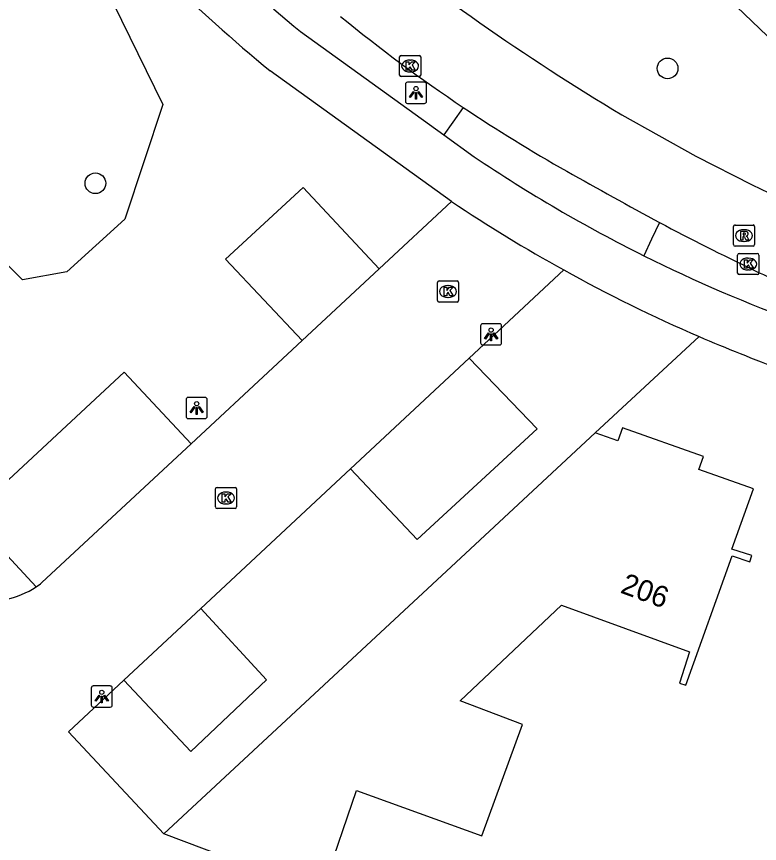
# Model space of a CAD drawing. Extents: x 155275 to 156263, y 382654 to 383635.
# Drawn here: x 155747.08 to 155782.2, y 383032.92 to 383071.98 of the extents above; entities that cross this region are included whole.
import ezdxf

# ---------------------------------------------------------------- set-up
doc = ezdxf.new("R2010")
doc.units = 0
for name, color, linetype in [('IMGEO_Berm_groen', 7, 'Continuous'), ('IMGEO_Boom', 7, 'Continuous'), ('IMGEO_Groenvoorziening', 7, 'Continuous'), ('IMGEO_Kolk', 7, 'Continuous'), ('IMGEO_Lichtpunt', 7, 'Continuous'), ('IMGEO_Pand', 7, 'Continuous'), ('IMGEO_Pand_nummerreeks', 7, 'Continuous'), ('IMGEO_Parkeervlak_open', 7, 'Continuous'), ('IMGEO_Rijbaan_lokaal_gesloten', 7, 'Continuous'), ('IMGEO_Rijbaan_lokaal_open', 7, 'Continuous'), ('IMGEO_Rioolput', 7, 'Continuous'), ('IMGEO_Voetpad_open', 7, 'Continuous')]:
    doc.layers.add(name, color=color, linetype=linetype)

msp = doc.modelspace()

# ---------------------------------------------------------------- linework, layer by layer
at = {"layer": 'IMGEO_Berm_groen'}
for points in [[(155812.91, 383066.171), (155809.833, 383066.391), (155801.367, 383066.998), (155792.138, 383071.742), (155786.195, 383067.61), (155775.328, 383078.007), (155762.855, 383086.013), (155746.776, 383104.071), (155742.231, 383112.533), (155736.041, 383119.787), (155734.812, 383124.613), (155732.465, 383124.934), (155728.264, 383135.475), (155728.221, 383137.957)], [(155779.344, 383056.868), (155774.441, 383052.316)]]:
    msp.add_lwpolyline(points, dxfattribs=at)
at = {"layer": 'IMGEO_Boom'}
for centre in [(155777.857, 383069.535), (155750.811, 383064.105)]:
    msp.add_circle(centre, 0.489, dxfattribs=at)
at = {"layer": 'IMGEO_Groenvoorziening'}
msp.add_lwpolyline([(155742.897, 383084.163), (155743.556, 383083.253), (155751.257, 383073.438), (155753.999, 383067.834), (155752.202, 383062.412), (155749.467, 383059.929), (155747.367, 383059.538), (155740.681, 383066.236), (155731.593, 383071.669), (155723.652, 383083.455), (155716.242, 383095.037), (155715.841, 383102.729), (155713.131, 383103.008)], dxfattribs=at)
at = {"layer": 'IMGEO_Kolk'}
for p, q in [((155765.262, 383070.147), (155766.114, 383070.147)), ((155765.187, 383069.221), (155765.187, 383070.073)), ((155765.675, 383069.927), (155765.7, 383069.927)), ((155766.188, 383070.073), (155766.188, 383069.221)), ((155765.698, 383069.367), (155765.673, 383069.367)), ((155766.114, 383069.147), (155765.262, 383069.147)), ((155781.17, 383059.865), (155781.17, 383060.717)), ((155781.245, 383060.791), (155782.097, 383060.791)), ((155782.171, 383060.717), (155782.171, 383059.865)), ((155781.658, 383060.571), (155781.683, 383060.571)), ((155781.681, 383060.011), (155781.656, 383060.011)), ((155782.097, 383059.791), (155781.245, 383059.791)), ((155766.978, 383058.567), (155766.978, 383059.419)), ((155767.053, 383059.493), (155767.905, 383059.493)), ((155767.466, 383059.273), (155767.491, 383059.273)), ((155767.979, 383059.419), (155767.979, 383058.567)), ((155767.905, 383058.493), (155767.053, 383058.493)), ((155767.489, 383058.713), (155767.464, 383058.713)), ((155756.486, 383048.813), (155756.486, 383049.665)), ((155756.561, 383049.739), (155757.413, 383049.739)), ((155756.974, 383049.519), (155756.999, 383049.519)), ((155757.487, 383049.665), (155757.487, 383048.813)), ((155757.413, 383048.739), (155756.561, 383048.739)), ((155756.997, 383048.959), (155756.972, 383048.959))]:
    msp.add_line(p, q, dxfattribs=at)
for points in [[(155765.262, 383070.147), (155766.114, 383070.147)], [(155765.187, 383069.221), (155765.187, 383070.073)], [(155765.508, 383069.847), (155765.631, 383069.847), (155765.631, 383069.696), (155765.761, 383069.847), (155765.925, 383069.847), (155765.779, 383069.696), (155765.932, 383069.447), (155765.78, 383069.447), (155765.695, 383069.611), (155765.631, 383069.544), (155765.631, 383069.447), (155765.508, 383069.447), (155765.508, 383069.847)], [(155766.188, 383070.073), (155766.188, 383069.221)], [(155766.114, 383069.147), (155765.262, 383069.147)], [(155781.17, 383059.865), (155781.17, 383060.717)], [(155781.245, 383060.791), (155782.097, 383060.791)], [(155782.171, 383060.717), (155782.171, 383059.865)], [(155781.491, 383060.491), (155781.614, 383060.491), (155781.614, 383060.34), (155781.744, 383060.491), (155781.908, 383060.491), (155781.762, 383060.34), (155781.915, 383060.091), (155781.763, 383060.091), (155781.678, 383060.255), (155781.614, 383060.188), (155781.614, 383060.091), (155781.491, 383060.091), (155781.491, 383060.491)], [(155782.097, 383059.791), (155781.245, 383059.791)], [(155766.978, 383058.567), (155766.978, 383059.419)], [(155767.053, 383059.493), (155767.905, 383059.493)], [(155767.299, 383059.193), (155767.422, 383059.193), (155767.422, 383059.042), (155767.552, 383059.193), (155767.716, 383059.193), (155767.57, 383059.042), (155767.723, 383058.793), (155767.571, 383058.793), (155767.486, 383058.957), (155767.422, 383058.89), (155767.422, 383058.793), (155767.299, 383058.793), (155767.299, 383059.193)], [(155767.979, 383059.419), (155767.979, 383058.567)], [(155767.905, 383058.493), (155767.053, 383058.493)], [(155756.486, 383048.813), (155756.486, 383049.665)], [(155756.561, 383049.739), (155757.413, 383049.739)], [(155756.807, 383049.439), (155756.93, 383049.439), (155756.93, 383049.288), (155757.06, 383049.439), (155757.224, 383049.439), (155757.078, 383049.288), (155757.231, 383049.039), (155757.079, 383049.039), (155756.994, 383049.203), (155756.93, 383049.136), (155756.93, 383049.039), (155756.807, 383049.039), (155756.807, 383049.439)], [(155757.487, 383049.665), (155757.487, 383048.813)], [(155757.413, 383048.739), (155756.561, 383048.739)]]:
    msp.add_lwpolyline(points, dxfattribs=at)
for centre, start, end in [((155765.264, 383070.071), 91.552, 178.448), ((155765.264, 383070.071), 91.552, 178.448), ((155766.112, 383070.071), 1.552, 88.448), ((155766.112, 383070.071), 1.552, 88.448), ((155765.264, 383069.223), 181.552, 268.448), ((155765.264, 383069.223), 181.552, 268.448), ((155766.112, 383069.223), 271.552, 358.448), ((155766.112, 383069.223), 271.552, 358.448), ((155781.247, 383060.715), 91.552, 178.448), ((155781.247, 383060.715), 91.552, 178.448), ((155782.095, 383060.715), 1.552, 88.448), ((155782.095, 383060.715), 1.552, 88.448), ((155781.247, 383059.867), 181.552, 268.448), ((155781.247, 383059.867), 181.552, 268.448), ((155782.095, 383059.867), 271.552, 358.448), ((155782.095, 383059.867), 271.552, 358.448), ((155767.055, 383059.417), 91.552, 178.448), ((155767.055, 383059.417), 91.552, 178.448), ((155767.903, 383059.417), 1.552, 88.448), ((155767.903, 383059.417), 1.552, 88.448), ((155767.055, 383058.569), 181.552, 268.448), ((155767.055, 383058.569), 181.552, 268.448), ((155767.903, 383058.569), 271.552, 358.448), ((155767.903, 383058.569), 271.552, 358.448), ((155756.563, 383049.663), 91.552, 178.448), ((155756.563, 383049.663), 91.552, 178.448), ((155757.411, 383049.663), 1.552, 88.448), ((155757.411, 383049.663), 1.552, 88.448), ((155756.563, 383048.815), 181.552, 268.448), ((155756.563, 383048.815), 181.552, 268.448), ((155757.411, 383048.815), 271.552, 358.448), ((155757.411, 383048.815), 271.552, 358.448)]:
    msp.add_arc(centre, 0.0765, start, end, dxfattribs=at)
for centre, major_axis, ratio, start_param, end_param in [((155765.674, 383069.647), (-0.387, 0.002), 0.722429, 4.712389, 7.853982), ((155765.699, 383069.647), (-0.39, 0.002), 0.717154, 1.570796, 4.712389), ((155781.657, 383060.291), (-0.387, 0.002), 0.722429, 4.712389, 7.853982), ((155781.682, 383060.291), (-0.39, 0.002), 0.717154, 1.570796, 4.712389), ((155767.465, 383058.993), (-0.387, 0.002), 0.722429, 4.712389, 7.853982), ((155767.49, 383058.993), (-0.39, 0.002), 0.717154, 1.570796, 4.712389), ((155756.973, 383049.239), (-0.387, 0.002), 0.722429, 4.712389, 7.853982), ((155756.998, 383049.239), (-0.39, 0.002), 0.717154, 1.570796, 4.712389)]:
    msp.add_ellipse(centre, major_axis=major_axis, ratio=ratio, start_param=start_param, end_param=end_param, dxfattribs=at)
at = {"layer": 'IMGEO_Lichtpunt'}
for p, q in [((155765.466, 383068.782), (155765.466, 383067.975)), ((155765.466, 383068.782), (155765.466, 383067.975)), ((155766.368, 383068.877), (155765.56, 383068.877)), ((155766.368, 383068.877), (155765.56, 383068.877)), ((155766.462, 383067.975), (155766.462, 383068.782)), ((155766.462, 383067.975), (155766.462, 383068.782)), ((155765.56, 383067.881), (155766.368, 383067.881)), ((155765.56, 383067.881), (155766.368, 383067.881)), ((155769.018, 383057.373), (155769.018, 383056.566)), ((155769.018, 383057.373), (155769.018, 383056.566)), ((155769.92, 383057.468), (155769.112, 383057.468)), ((155769.92, 383057.468), (155769.112, 383057.468)), ((155770.014, 383056.566), (155770.014, 383057.373)), ((155770.014, 383056.566), (155770.014, 383057.373)), ((155769.112, 383056.472), (155769.92, 383056.472)), ((155769.112, 383056.472), (155769.92, 383056.472)), ((155755.099, 383053.893), (155755.099, 383053.086)), ((155755.099, 383053.893), (155755.099, 383053.086)), ((155756.001, 383053.988), (155755.193, 383053.988)), ((155756.001, 383053.988), (155755.193, 383053.988)), ((155756.095, 383053.086), (155756.095, 383053.893)), ((155756.095, 383053.086), (155756.095, 383053.893)), ((155755.193, 383052.992), (155756.001, 383052.992)), ((155755.193, 383052.992), (155756.001, 383052.992)), ((155750.614, 383040.261), (155750.614, 383039.454)), ((155750.614, 383040.261), (155750.614, 383039.454)), ((155751.516, 383040.356), (155750.708, 383040.356)), ((155751.516, 383040.356), (155750.708, 383040.356)), ((155751.61, 383039.454), (155751.61, 383040.261)), ((155751.61, 383039.454), (155751.61, 383040.261)), ((155750.708, 383039.36), (155751.516, 383039.36)), ((155750.708, 383039.36), (155751.516, 383039.36))]:
    msp.add_line(p, q, dxfattribs=at)
for points in [[(155765.84, 383068.446), (155765.879, 383068.418), (155765.691, 383068.156), (155765.653, 383068.183), (155765.84, 383068.446)], [(155765.942, 383068.398), (155765.989, 383068.398), (155765.989, 383068.076), (155765.942, 383068.076), (155765.942, 383068.398)], [(155766.052, 383068.418), (155766.09, 383068.445), (155766.277, 383068.183), (155766.238, 383068.155), (155766.052, 383068.418)], [(155769.392, 383057.037), (155769.431, 383057.009), (155769.243, 383056.747), (155769.205, 383056.774), (155769.392, 383057.037)], [(155769.494, 383056.989), (155769.541, 383056.989), (155769.541, 383056.667), (155769.494, 383056.667), (155769.494, 383056.989)], [(155769.604, 383057.009), (155769.642, 383057.036), (155769.829, 383056.774), (155769.79, 383056.746), (155769.604, 383057.009)], [(155755.473, 383053.557), (155755.512, 383053.529), (155755.324, 383053.267), (155755.286, 383053.294), (155755.473, 383053.557)], [(155755.575, 383053.509), (155755.622, 383053.509), (155755.622, 383053.187), (155755.575, 383053.187), (155755.575, 383053.509)], [(155755.685, 383053.529), (155755.723, 383053.556), (155755.91, 383053.294), (155755.871, 383053.266), (155755.685, 383053.529)], [(155750.988, 383039.925), (155751.027, 383039.897), (155750.839, 383039.635), (155750.801, 383039.662), (155750.988, 383039.925)], [(155751.09, 383039.877), (155751.137, 383039.877), (155751.137, 383039.555), (155751.09, 383039.555), (155751.09, 383039.877)], [(155751.2, 383039.897), (155751.238, 383039.924), (155751.425, 383039.662), (155751.386, 383039.634), (155751.2, 383039.897)]]:
    msp.add_lwpolyline(points, dxfattribs=at)
for centre in [(155765.965, 383068.58), (155769.517, 383057.171), (155755.598, 383053.691), (155751.113, 383040.059)]:
    msp.add_circle(centre, 0.0994, dxfattribs=at)
for centre, start, end in [((155765.56, 383068.782), 90, 180), ((155765.56, 383068.782), 90, 180), ((155766.368, 383068.782), 0, 90), ((155766.368, 383068.782), 0, 90), ((155765.56, 383067.975), 180, 270), ((155765.56, 383067.975), 180, 270), ((155766.368, 383067.975), 270, 0), ((155766.368, 383067.975), 270, 360), ((155769.112, 383057.373), 90, 180), ((155769.112, 383057.373), 90, 180), ((155769.92, 383057.373), 0, 90), ((155769.92, 383057.373), 0, 90), ((155769.112, 383056.566), 180, 270), ((155769.112, 383056.566), 180, 270), ((155769.92, 383056.566), 270, 0), ((155769.92, 383056.566), 270, 360), ((155755.193, 383053.893), 90, 180), ((155755.193, 383053.893), 90, 180), ((155756.001, 383053.893), 0, 90), ((155756.001, 383053.893), 0, 90), ((155755.193, 383053.086), 180, 270), ((155755.193, 383053.086), 180, 270), ((155756.001, 383053.086), 270, 0), ((155756.001, 383053.086), 270, 360), ((155750.708, 383040.261), 90, 180), ((155750.708, 383040.261), 90, 180), ((155751.516, 383040.261), 0, 90), ((155751.516, 383040.261), 0, 90), ((155750.708, 383039.454), 180, 270), ((155750.708, 383039.454), 180, 270), ((155751.516, 383039.454), 270, 0), ((155751.516, 383039.454), 270, 360)]:
    msp.add_arc(centre, 0.0946, start, end, dxfattribs=at)
at = {"layer": 'IMGEO_Pand'}
for points in [[(155761.488, 383030.572), (155761.65, 383031.045), (155763.158, 383035.426), (155769.073, 383033.274), (155770.993, 383038.539), (155768.052, 383039.655), (155772.843, 383044.181), (155778.895, 383041.966), (155778.42, 383040.49), (155778.719, 383040.394), (155780.912, 383046.512), (155781.738, 383046.226), (155781.833, 383046.518), (155780.902, 383046.822), (155781.914, 383049.664), (155779.333, 383050.584), (155779.552, 383051.196), (155775.727, 383052.559), (155775.506, 383051.937), (155774.441, 383052.316)], [(155774.441, 383052.316), (155767.621, 383045.984), (155754.044, 383033.378)], [(155761.488, 383030.572), (155754.044, 383033.378)]]:
    msp.add_lwpolyline(points, dxfattribs=at)
at = {"layer": 'IMGEO_Parkeervlak_open'}
for points in [[(155760.588, 383056.683), (155756.964, 383060.529), (155760.626, 383063.912), (155764.227, 383060.067)], [(155762.866, 383050.613), (155766.019, 383047.276), (155771.696, 383052.498), (155768.485, 383055.851)], [(155748.013, 383045.041), (155744.881, 383048.414), (155752.176, 383055.188), (155755.336, 383051.798)], [(155752.158, 383040.632), (155755.317, 383037.269), (155758.902, 383040.641), (155755.794, 383044.021)]]:
    msp.add_lwpolyline(points, dxfattribs=at)
at = {"layer": 'IMGEO_Rijbaan_lokaal_gesloten'}
msp.add_lwpolyline([(155775.703, 383067.34), (155779.187, 383065.387), (155781.855, 383064.031)], dxfattribs=at)
for centre, radius, start, end in [((155831.621, 383161.055), 109.13, 230.76947, 239.17607), ((155810.649, 383131.036), 76.254, 230.75141, 236.17006), ((155810.185, 383130.419), 75.484, 236.20193, 240.56871), ((155906.518, 383300.772), 271.188, 240.52793, 241.5871), ((155818.231, 383138.767), 83.119, 244.04642, 248.89274), ((155838.195, 383177.14), 129.945, 242.14535, 244.34433), ((155797.597, 383093.028), 36.549, 244.6246, 250.8943)]:
    msp.add_arc(centre, radius, start, end, dxfattribs=at)
at = {"layer": 'IMGEO_Rijbaan_lokaal_open'}
for points in [[(155768.196, 383067.692), (155767.707, 383066.995), (155767.283, 383066.391)], [(155767.283, 383066.391), (155768.712, 383065.361)], [(155767.647, 383063.248), (155764.227, 383060.067)], [(155777.481, 383062.251), (155777.103, 383061.46), (155776.733, 383060.685)], [(155764.227, 383060.067), (155760.588, 383056.683)], [(155768.485, 383055.851), (155772.949, 383060.012)], [(155760.588, 383056.683), (155759.198, 383055.39), (155755.336, 383051.798)], [(155762.866, 383050.613), (155768.485, 383055.851)], [(155755.336, 383051.798), (155748.283, 383045.239)], [(155755.794, 383044.021), (155762.866, 383050.613)], [(155752.158, 383040.632), (155755.794, 383044.021)], [(155754.044, 383033.378), (155749.542, 383038.194), (155752.158, 383040.632)]]:
    msp.add_lwpolyline(points, dxfattribs=at)
for centre, radius, start, end in [((155808.421, 383124.259), 71.033, 236.012, 243.50622), ((155808.187, 383123.708), 72.794, 236.15752, 241.04807), ((155745.875, 383048.233), 3.842, 210.1453, 303.8057), ((155745.848, 383048.276), 3.892, 303.7887, 308.719)]:
    msp.add_arc(centre, radius, start, end, dxfattribs=at)
at = {"layer": 'IMGEO_Rioolput'}
for p, q in [((155780.97, 383061.209), (155780.97, 383062.061)), ((155781.045, 383062.135), (155781.897, 383062.135)), ((155781.458, 383061.915), (155781.483, 383061.915)), ((155781.971, 383062.061), (155781.971, 383061.209)), ((155781.897, 383061.135), (155781.045, 383061.135)), ((155781.481, 383061.355), (155781.456, 383061.355))]:
    msp.add_line(p, q, dxfattribs=at)
for points in [[(155780.97, 383061.209), (155780.97, 383062.061)], [(155781.045, 383062.135), (155781.897, 383062.135)], [(155781.971, 383062.061), (155781.971, 383061.209)], [(155781.559, 383061.833), (155781.307, 383061.835), (155781.307, 383061.435)], [(155781.307, 383061.435), (155781.431, 383061.435), (155781.431, 383061.597), (155781.442, 383061.597)], [(155781.485, 383061.754), (155781.431, 383061.754), (155781.431, 383061.673)], [(155781.431, 383061.673), (155781.483, 383061.673)], [(155781.489, 383061.568), (155781.56, 383061.435), (155781.7, 383061.435), (155781.635, 383061.561)], [(155781.897, 383061.135), (155781.045, 383061.135)]]:
    msp.add_lwpolyline(points, dxfattribs=at)
for centre, radius, start, end in [((155781.047, 383062.059), 0.0765, 91.552, 178.448), ((155781.047, 383062.059), 0.0765, 91.552, 178.448), ((155781.895, 383062.059), 0.0765, 1.552, 88.448), ((155781.895, 383062.059), 0.0765, 1.552, 88.448), ((155781.441, 383061.544), 0.0533, 26.0293, 88.6989), ((155781.467, 383061.862), 0.19, 274.7715, 282.9687), ((155781.491, 383061.658), 0.0964, 77.0061, 93.1865), ((155781.505, 383061.715), 0.0378, 276.6634, 79.6772), ((155781.558, 383061.723), 0.109, 350.3612, 89.416), ((155781.556, 383061.723), 0.112, 277.5842, 350.9817), ((155781.54, 383061.508), 0.108, 29.5134, 73.7905), ((155781.047, 383061.211), 0.0765, 181.552, 268.448), ((155781.047, 383061.211), 0.0765, 181.552, 268.448), ((155781.895, 383061.211), 0.0765, 271.552, 358.448), ((155781.895, 383061.211), 0.0765, 271.552, 358.448)]:
    msp.add_arc(centre, radius, start, end, dxfattribs=at)
for centre, major_axis, ratio, start_param, end_param in [((155781.457, 383061.635), (-0.387, 0.002), 0.722429, 4.712389, 7.853982), ((155781.482, 383061.635), (-0.39, 0.002), 0.717154, 1.570796, 4.712389)]:
    msp.add_ellipse(centre, major_axis=major_axis, ratio=ratio, start_param=start_param, end_param=end_param, dxfattribs=at)
at = {"layer": 'IMGEO_Voetpad_open'}
for points in [[(155760.513, 383071.272), (155767.283, 383066.391)], [(155767.647, 383063.248), (155759.074, 383069.413)]]:
    msp.add_lwpolyline(points, dxfattribs=at)
for centre, radius, start, end in [((155823.459, 383147.049), 98.51, 222.60047, 230.28458), ((155823.092, 383146.671), 100.334, 222.56561, 230.354), ((155808.534, 383124.542), 71.337, 243.52683, 250.02575), ((155808.264, 383123.768), 72.883, 241.01757, 246.62182), ((155808.525, 383124.418), 73.583, 246.63582, 249.9227)]:
    msp.add_arc(centre, radius, start, end, dxfattribs=at)

# ---------------------------------------------------------------- texts
at = {"layer": 'IMGEO_Pand_nummerreeks'}
msp.add_text('206', height=1, rotation=339.8976, dxfattribs=at).set_placement((155775.579, 383044.777))

doc.saveas('drawing.dxf')
